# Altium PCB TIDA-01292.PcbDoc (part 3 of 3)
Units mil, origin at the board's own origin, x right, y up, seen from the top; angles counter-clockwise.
Board outline 6102.36 x 3543.31 mil, 2 copper layers (Top Layer, Bottom Layer), stack 64.8 mil thick; 118 components, 43 nets, 376 pads, 3910 vias.
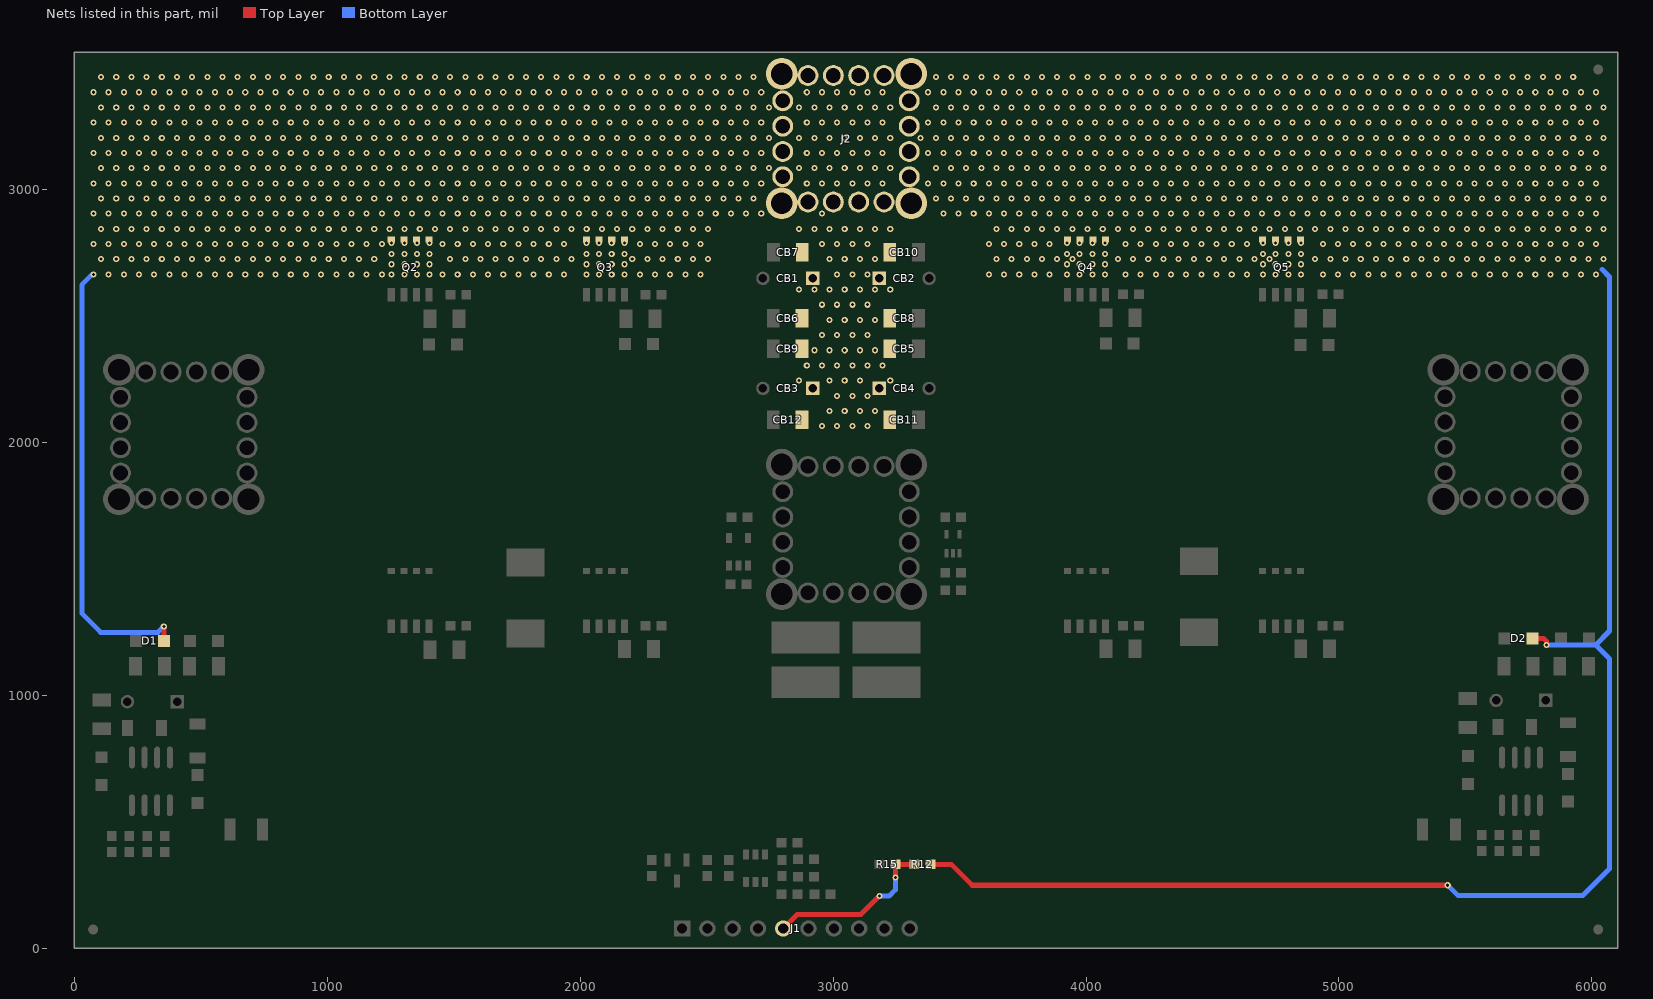
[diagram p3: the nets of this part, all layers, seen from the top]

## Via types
v1: diameter 24, hole 12, Top Layer to Bottom Layer, 3910 vias

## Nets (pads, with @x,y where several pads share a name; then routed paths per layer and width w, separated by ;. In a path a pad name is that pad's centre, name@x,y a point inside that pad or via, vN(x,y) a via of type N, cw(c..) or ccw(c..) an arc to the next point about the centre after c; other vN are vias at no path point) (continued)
VBAT: CB1.1 CB2.1 CB3.1 CB4.1 CB5.1 CB6.1 CB7.1 CB8.1 CB9.1 CB10.1 CB11.1 CB12.1 D1.2 D2.2 J2.1 pad.1@2797.2,2946.03 pad.1@2797.2,3457.84 pad.1@3309.01,2946.03 pad.1@3309.01,3457.84 Q2.5 Q2.6 Q2.7 Q2.8 Q3.5 Q3.6 Q3.7 Q3.8 Q4.5 Q4.6 Q4.7 Q4.8 Q5.5 Q5.6 Q5.7 Q5.8 R12.2 | length 7261.9
  Top Layer w20: D1.2@354.1,1215.6 v1(354.1,1273.6) ; R12.2@3384.65,337.74 R12.2@3384.65,332.74 3467.26,332.74 3550,250 v1(5430,250) ; D2.2@5765.12,1225.51 5809.49,1225.51 5820,1215 v1(5820,1200)
  Bottom Layer w20: v1@71.15,2665 30,2623.85 30,1325 105,1250 330.5,1250 v1(354.1,1273.6) ; v1(5430,250) 5470,210 5965,210 6070,315 6070,1145 6015,1200 ; v1(5820,1200) 6015,1200 ; 6040,2685 6070,2655 6070,1255 6015,1200
  other v1: 2956.15,2065 3016.15,2065 3076.15,2065 3136.15,2065 2986.15,2125 3046.15,2125 3106.15,2125 3166.15,2125 3016.15,2185 3076.15,2185 3136.15,2185 2866.15,2245 2986.15,2245 3046.15,2245 3106.15,2245 3226.15,2245 2896.15,2305 2956.15,2305 3016.15,2305 3076.15,2305 3136.15,2305 3196.15,2305 2926.15,2365 2986.15,2365 3046.15,2365 3106.15,2365 3166.15,2365 2956.15,2425 3016.15,2425 3076.15,2425 3136.15,2425 2986.15,2485 3046.15,2485 3106.15,2485 3166.15,2485 2956.15,2545 3016.15,2545 3076.15,2545 3136.15,2545 2866.15,2605 2926.15,2605 2986.15,2605 3046.15,2605 3106.15,2605 3166.15,2605 3226.15,2605 76.15,2665 136.15,2665 196.15,2665 256.15,2665 316.15,2665 376.15,2665 436.15,2665 496.15,2665 556.15,2665 616.15,2665 676.15,2665 736.15,2665 796.15,2665 856.15,2665 916.15,2665 976.15,2665 1036.15,2665 1096.15,2665 1156.15,2665 1216.15,2665 1255,2665 1305,2665 1355,2665 1405,2665 1456.15,2665 1516.15,2665 1576.15,2665 1636.15,2665 1696.15,2665 1756.15,2665 1816.15,2665 1876.15,2665 1936.15,2665 2025,2665 2075,2665 2125,2665 2175,2665 2236.15,2665 2296.15,2665 2356.15,2665 2416.15,2665 2476.15,2665 3016.15,2665 3076.15,2665 3136.15,2665 3616.15,2665 3676.15,2665 3736.15,2665 3796.15,2665 3856.15,2665 3925,2665 3975,2665 4025,2665 4075,2665 4156.15,2665 4216.15,2665 4276.15,2665 4336.15,2665 4396.15,2665 4456.15,2665 4516.15,2665 4576.15,2665 4636.15,2665 4700,2665 4750,2665 4800,2665 4850,2665 4936.15,2665 4996.15,2665 5056.15,2665 5116.15,2665 5176.15,2665 5236.15,2665 5296.15,2665 5356.15,2665 5416.15,2665 5476.15,2665 5536.15,2665 5596.15,2665 5656.15,2665 5716.15,2665 5776.15,2665 5836.15,2665 5896.15,2665 5956.15,2665 6016.15,2665 1255,2705 1305,2705 1355,2705 1405,2705 2025,2705 2075,2705 2125,2705 2175,2705 3925,2705 3975,2705 4025,2705 4075,2705 4700,2705 4750,2705 4800,2705 4850,2705 106.15,2725 166.15,2725 226.15,2725 286.15,2725 346.15,2725 406.15,2725 466.15,2725 526.15,2725 586.15,2725 646.15,2725 706.15,2725 766.15,2725 826.15,2725 886.15,2725 946.15,2725 1006.15,2725 1066.15,2725 1126.15,2725 1186.15,2725 1486.15,2725 1546.15,2725 1606.15,2725 1666.15,2725 1726.15,2725 1786.15,2725 1846.15,2725 1906.15,2725 1966.15,2725 2206.15,2725 2266.15,2725 2326.15,2725 2386.15,2725 2446.15,2725 2506.15,2725 2986.15,2725 3046.15,2725 3106.15,2725 3166.15,2725 3646.15,2725 3706.15,2725 3766.15,2725 3826.15,2725 3886.15,2725 3946.15,2725 4126.15,2725 4186.15,2725 4246.15,2725 4306.15,2725 4366.15,2725 4426.15,2725 4486.15,2725 4546.15,2725 4606.15,2725 4666.15,2725 4726.15,2725 4906.15,2725 4966.15,2725 5026.15,2725 5086.15,2725 5146.15,2725 5206.15,2725 5266.15,2725 5326.15,2725 5386.15,2725 5446.15,2725 5506.15,2725 5566.15,2725 5626.15,2725 5686.15,2725 5746.15,2725 5806.15,2725 5866.15,2725 5926.15,2725 5986.15,2725 6046.15,2725 1255,2745 1305,2745 1355,2745 1405,2745 2025,2745 2075,2745 2125,2745 2175,2745 3925,2745 3975,2745 4025,2745 4075,2745 4700,2745 4750,2745 4800,2745 4850,2745 76.15,2785 136.15,2785 196.15,2785 256.15,2785 316.15,2785 376.15,2785 436.15,2785 496.15,2785 556.15,2785 616.15,2785 676.15,2785 736.15,2785 796.15,2785 856.15,2785 916.15,2785 976.15,2785 1036.15,2785 1096.15,2785 1156.15,2785 1216.15,2785 1456.15,2785 1516.15,2785 1576.15,2785 1636.15,2785 1696.15,2785 1756.15,2785 1816.15,2785 1876.15,2785 1936.15,2785 2236.15,2785 2296.15,2785 2356.15,2785 2416.15,2785 2476.15,2785 2956.15,2785 3016.15,2785 3076.15,2785 3136.15,2785 3616.15,2785 3676.15,2785 3736.15,2785 3796.15,2785 3856.15,2785 4156.15,2785 4216.15,2785 4276.15,2785 4336.15,2785 4396.15,2785 4456.15,2785 4516.15,2785 4576.15,2785 4636.15,2785 4936.15,2785 4996.15,2785 5056.15,2785 5116.15,2785 5176.15,2785 5236.15,2785 5296.15,2785 5356.15,2785 5416.15,2785 5476.15,2785 5536.15,2785 5596.15,2785 5656.15,2785 5716.15,2785 5776.15,2785 5836.15,2785 5896.15,2785 5956.15,2785 6016.15,2785 1255,2789 1305,2789 1355,2789 1405,2789 2025,2789 2075,2789 2125,2789 2175,2789 3925,2789 3975,2789 4025,2789 4075,2789 4700,2789 4750,2789 4800,2789 4850,2789 106.15,2845 166.15,2845 226.15,2845 286.15,2845 346.15,2845 406.15,2845 466.15,2845 526.15,2845 586.15,2845 646.15,2845 706.15,2845 766.15,2845 826.15,2845 886.15,2845 946.15,2845 1006.15,2845 1066.15,2845 1126.15,2845 1186.15,2845 1246.15,2845 1306.15,2845 1366.15,2845 1426.15,2845 1486.15,2845 1546.15,2845 1606.15,2845 1666.15,2845 1726.15,2845 1786.15,2845 1846.15,2845 1906.15,2845 1966.15,2845 2026.15,2845 2086.15,2845 2146.15,2845 2206.15,2845 2266.15,2845 2326.15,2845 2386.15,2845 2446.15,2845 2506.15,2845 2866.15,2845 2926.15,2845 2986.15,2845 3046.15,2845 3106.15,2845 3166.15,2845 3226.15,2845 3646.15,2845 3706.15,2845 3766.15,2845 3826.15,2845 3886.15,2845 3946.15,2845 4006.15,2845 4066.15,2845 4126.15,2845 4186.15,2845 4246.15,2845 4306.15,2845 4366.15,2845 4426.15,2845 4486.15,2845 4546.15,2845 4606.15,2845 4666.15,2845 4726.15,2845 4786.15,2845 4846.15,2845 4906.15,2845 4966.15,2845 5026.15,2845 5086.15,2845 5146.15,2845 5206.15,2845 5266.15,2845 5326.15,2845 5386.15,2845 5446.15,2845 5506.15,2845 5566.15,2845 5626.15,2845 5686.15,2845 5746.15,2845 5806.15,2845 5866.15,2845 5926.15,2845 5986.15,2845 6046.15,2845 76.15,2905 136.15,2905 196.15,2905 256.15,2905 316.15,2905 376.15,2905 436.15,2905 496.15,2905 556.15,2905 616.15,2905 676.15,2905 736.15,2905 796.15,2905 856.15,2905 916.15,2905 976.15,2905 1036.15,2905 1096.15,2905 1156.15,2905 1216.15,2905 1276.15,2905 1336.15,2905 1396.15,2905 1456.15,2905 1516.15,2905 1576.15,2905 1636.15,2905 1696.15,2905 1756.15,2905 1816.15,2905 1876.15,2905 1936.15,2905 1996.15,2905 2056.15,2905 2116.15,2905 2176.15,2905 2236.15,2905 2296.15,2905 2356.15,2905 2416.15,2905 2476.15,2905 2536.15,2905 2596.15,2905 2656.15,2905 2716.15,2905 2956.15,2905 3436.15,2905 3496.15,2905 3556.15,2905 3616.15,2905 3676.15,2905 3736.15,2905 3796.15,2905 3856.15,2905 3916.15,2905 3976.15,2905 4036.15,2905 4096.15,2905 4156.15,2905 4216.15,2905 4276.15,2905 4336.15,2905 4396.15,2905 4456.15,2905 4516.15,2905 4576.15,2905 4636.15,2905 4696.15,2905 4756.15,2905 4816.15,2905 4876.15,2905 4936.15,2905 4996.15,2905 5056.15,2905 5116.15,2905 5176.15,2905 5236.15,2905 5296.15,2905 5356.15,2905 5416.15,2905 5476.15,2905 5536.15,2905 5596.15,2905 5656.15,2905 5716.15,2905 5776.15,2905 5836.15,2905 5896.15,2905 5956.15,2905 6016.15,2905 106.15,2965 166.15,2965 226.15,2965 286.15,2965 346.15,2965 406.15,2965 466.15,2965 526.15,2965 586.15,2965 646.15,2965 706.15,2965 766.15,2965 826.15,2965 886.15,2965 946.15,2965 1006.15,2965 1066.15,2965 1126.15,2965 1186.15,2965 1246.15,2965 1306.15,2965 1366.15,2965 1426.15,2965 1486.15,2965 1546.15,2965 1606.15,2965 1666.15,2965 1726.15,2965 1786.15,2965 1846.15,2965 1906.15,2965 1966.15,2965 2026.15,2965 2086.15,2965 2146.15,2965 2206.15,2965 2266.15,2965 2326.15,2965 2386.15,2965 2446.15,2965 2506.15,2965 2566.15,2965 2626.15,2965 2686.15,2965 3406.15,2965 3466.15,2965 3526.15,2965 3586.15,2965 3646.15,2965 3706.15,2965 3766.15,2965 3826.15,2965 3886.15,2965 3946.15,2965 4006.15,2965 4066.15,2965 4126.15,2965 4186.15,2965 4246.15,2965 4306.15,2965 4366.15,2965 4426.15,2965 4486.15,2965 4546.15,2965 4606.15,2965 4666.15,2965 4726.15,2965 4786.15,2965 4846.15,2965 4906.15,2965 4966.15,2965 5026.15,2965 5086.15,2965 5146.15,2965 5206.15,2965 5266.15,2965 5326.15,2965 5386.15,2965 5446.15,2965 5506.15,2965 5566.15,2965 5626.15,2965 5686.15,2965 5746.15,2965 5806.15,2965 5866.15,2965 5926.15,2965 5986.15,2965 6046.15,2965 76.15,3025 136.15,3025 196.15,3025 256.15,3025 316.15,3025 376.15,3025 436.15,3025 496.15,3025 556.15,3025 616.15,3025 676.15,3025 736.15,3025 796.15,3025 856.15,3025 916.15,3025 976.15,3025 1036.15,3025 1096.15,3025 1156.15,3025 1216.15,3025 1276.15,3025 1336.15,3025 1396.15,3025 1456.15,3025 1516.15,3025 1576.15,3025 1636.15,3025 1696.15,3025 1756.15,3025 1816.15,3025 1876.15,3025 1936.15,3025 1996.15,3025 2056.15,3025 2116.15,3025 2176.15,3025 2236.15,3025 2296.15,3025 2356.15,3025 2416.15,3025 2476.15,3025 2536.15,3025 2596.15,3025 2656.15,3025 2716.15,3025 2896.15,3025 2956.15,3025 3016.15,3025 3076.15,3025 3136.15,3025 3196.15,3025 3376.15,3025 3436.15,3025 3496.15,3025 3556.15,3025 3616.15,3025 3676.15,3025 3736.15,3025 3796.15,3025 3856.15,3025 3916.15,3025 3976.15,3025 4036.15,3025 4096.15,3025 4156.15,3025 4216.15,3025 4276.15,3025 4336.15,3025 4396.15,3025 4456.15,3025 4516.15,3025 4576.15,3025 4636.15,3025 4696.15,3025 4756.15,3025 4816.15,3025 4876.15,3025 4936.15,3025 4996.15,3025 5056.15,3025 5116.15,3025 5176.15,3025 5236.15,3025 5296.15,3025 5356.15,3025 5416.15,3025 5476.15,3025 5536.15,3025 5596.15,3025 5656.15,3025 5716.15,3025 5776.15,3025 5836.15,3025 5896.15,3025 5956.15,3025 6016.15,3025 106.15,3085 166.15,3085 226.15,3085 286.15,3085 346.15,3085 406.15,3085 466.15,3085 526.15,3085 586.15,3085 646.15,3085 706.15,3085 766.15,3085 826.15,3085 886.15,3085 946.15,3085 1006.15,3085 1066.15,3085 1126.15,3085 1186.15,3085 1246.15,3085 1306.15,3085 1366.15,3085 1426.15,3085 1486.15,3085 1546.15,3085 1606.15,3085 1666.15,3085 1726.15,3085 1786.15,3085 1846.15,3085 1906.15,3085 1966.15,3085 2026.15,3085 2086.15,3085 2146.15,3085 2206.15,3085 2266.15,3085 2326.15,3085 2386.15,3085 2446.15,3085 2506.15,3085 2566.15,3085 2626.15,3085 2686.15,3085 2746.15,3085 2866.15,3085 2926.15,3085 2986.15,3085 3046.15,3085 3106.15,3085 3166.15,3085 3226.15,3085 3406.15,3085 3466.15,3085 3526.15,3085 3586.15,3085 3646.15,3085 3706.15,3085 3766.15,3085 3826.15,3085 3886.15,3085 3946.15,3085 4006.15,3085 4066.15,3085 4126.15,3085 4186.15,3085 4246.15,3085 4306.15,3085 4366.15,3085 4426.15,3085 4486.15,3085 4546.15,3085 4606.15,3085 4666.15,3085 4726.15,3085 4786.15,3085 4846.15,3085 4906.15,3085 4966.15,3085 5026.15,3085 5086.15,3085 5146.15,3085 5206.15,3085 5266.15,3085 5326.15,3085 5386.15,3085 5446.15,3085 5506.15,3085 5566.15,3085 5626.15,3085 5686.15,3085 5746.15,3085 5806.15,3085 5866.15,3085 5926.15,3085 5986.15,3085 6046.15,3085 76.15,3145 136.15,3145 196.15,3145 256.15,3145 316.15,3145 376.15,3145 436.15,3145 496.15,3145 556.15,3145 616.15,3145 676.15,3145 736.15,3145 796.15,3145 856.15,3145 916.15,3145 976.15,3145 1036.15,3145 1096.15,3145 1156.15,3145 1216.15,3145 1276.15,3145 1336.15,3145 1396.15,3145 1456.15,3145 1516.15,3145 1576.15,3145 1636.15,3145 1696.15,3145 1756.15,3145 1816.15,3145 1876.15,3145 1936.15,3145 1996.15,3145 2056.15,3145 2116.15,3145 2176.15,3145 2236.15,3145 2296.15,3145 2356.15,3145 2416.15,3145 2476.15,3145 2536.15,3145 2596.15,3145 2656.15,3145 2716.15,3145 2896.15,3145 2956.15,3145 3016.15,3145 3076.15,3145 3136.15,3145 3196.15,3145 3376.15,3145 3436.15,3145 3496.15,3145 3556.15,3145 3616.15,3145 3676.15,3145 3736.15,3145 3796.15,3145 3856.15,3145 3916.15,3145 3976.15,3145 4036.15,3145 4096.15,3145 4156.15,3145 4216.15,3145 4276.15,3145 4336.15,3145 4396.15,3145 4456.15,3145 4516.15,3145 4576.15,3145 4636.15,3145 4696.15,3145 4756.15,3145 4816.15,3145 4876.15,3145 4936.15,3145 4996.15,3145 5056.15,3145 5116.15,3145 5176.15,3145 5236.15,3145 5296.15,3145 5356.15,3145 5416.15,3145 5476.15,3145 5536.15,3145 5596.15,3145 5656.15,3145 5716.15,3145 5776.15,3145 5836.15,3145 5896.15,3145 5956.15,3145 6016.15,3145 106.15,3205 166.15,3205 226.15,3205 286.15,3205 346.15,3205 406.15,3205 466.15,3205 526.15,3205 586.15,3205 646.15,3205 706.15,3205 766.15,3205 826.15,3205 886.15,3205 946.15,3205 1006.15,3205 1066.15,3205 1126.15,3205 1186.15,3205 1246.15,3205 1306.15,3205 1366.15,3205 1426.15,3205 1486.15,3205 1546.15,3205 1606.15,3205 1666.15,3205 1726.15,3205 1786.15,3205 1846.15,3205 1906.15,3205 1966.15,3205 2026.15,3205 2086.15,3205 2146.15,3205 2206.15,3205 2266.15,3205 2326.15,3205 2386.15,3205 2446.15,3205 2506.15,3205 2566.15,3205 2626.15,3205 2686.15,3205 2746.15,3205 2866.15,3205 2926.15,3205 2986.15,3205 3046.15,3205 3106.15,3205 3166.15,3205 3226.15,3205 3346.15,3205 3406.15,3205 3466.15,3205 3526.15,3205 3586.15,3205 3646.15,3205 3706.15,3205 3766.15,3205 3826.15,3205 3886.15,3205 3946.15,3205 4006.15,3205 4066.15,3205 4126.15,3205 4186.15,3205 4246.15,3205 4306.15,3205 4366.15,3205 4426.15,3205 4486.15,3205 4546.15,3205 4606.15,3205 4666.15,3205 4726.15,3205 4786.15,3205 4846.15,3205 4906.15,3205 4966.15,3205 5026.15,3205 5086.15,3205 5146.15,3205 5206.15,3205 5266.15,3205 5326.15,3205 5386.15,3205 5446.15,3205 5506.15,3205 5566.15,3205 5626.15,3205 5686.15,3205 5746.15,3205 5806.15,3205 5866.15,3205 5926.15,3205 5986.15,3205 6046.15,3205 76.15,3265 136.15,3265 196.15,3265 256.15,3265 316.15,3265 376.15,3265 436.15,3265 496.15,3265 556.15,3265 616.15,3265 676.15,3265 736.15,3265 796.15,3265 856.15,3265 916.15,3265 976.15,3265 1036.15,3265 1096.15,3265 1156.15,3265 1216.15,3265 1276.15,3265 1336.15,3265 1396.15,3265 1456.15,3265 1516.15,3265 1576.15,3265 1636.15,3265 1696.15,3265 1756.15,3265 1816.15,3265 1876.15,3265 1936.15,3265 1996.15,3265 2056.15,3265 2116.15,3265 2176.15,3265 2236.15,3265 2296.15,3265 2356.15,3265 2416.15,3265 2476.15,3265 2536.15,3265 2596.15,3265 2656.15,3265 2716.15,3265 2896.15,3265 2956.15,3265 3016.15,3265 3076.15,3265 3136.15,3265 3196.15,3265 3376.15,3265 3436.15,3265 3496.15,3265 3556.15,3265 3616.15,3265 3676.15,3265 3736.15,3265 3796.15,3265 3856.15,3265 3916.15,3265 3976.15,3265 4036.15,3265 4096.15,3265 4156.15,3265 4216.15,3265 4276.15,3265 4336.15,3265 4396.15,3265 4456.15,3265 4516.15,3265 4576.15,3265 4636.15,3265 4696.15,3265 4756.15,3265 4816.15,3265 4876.15,3265 4936.15,3265 4996.15,3265 5056.15,3265 5116.15,3265 5176.15,3265 5236.15,3265 5296.15,3265 5356.15,3265 5416.15,3265 5476.15,3265 5536.15,3265 5596.15,3265 5656.15,3265 5716.15,3265 5776.15,3265 5836.15,3265 5896.15,3265 5956.15,3265 6016.15,3265 106.15,3325 166.15,3325 226.15,3325 286.15,3325 346.15,3325 406.15,3325 466.15,3325 526.15,3325 586.15,3325 646.15,3325 706.15,3325 766.15,3325 826.15,3325 886.15,3325 946.15,3325 1006.15,3325 1066.15,3325 1126.15,3325 1186.15,3325 1246.15,3325 1306.15,3325 1366.15,3325 1426.15,3325 1486.15,3325 1546.15,3325 1606.15,3325 1666.15,3325 1726.15,3325 1786.15,3325 1846.15,3325 1906.15,3325 1966.15,3325 2026.15,3325 2086.15,3325 2146.15,3325 2206.15,3325 2266.15,3325 2326.15,3325 2386.15,3325 2446.15,3325 2506.15,3325 2566.15,3325 2626.15,3325 2686.15,3325 2746.15,3325 2866.15,3325 2926.15,3325 2986.15,3325 3046.15,3325 3106.15,3325 3166.15,3325 3226.15,3325 3406.15,3325 3466.15,3325 3526.15,3325 3586.15,3325 3646.15,3325 3706.15,3325 3766.15,3325 3826.15,3325 3886.15,3325 3946.15,3325 4006.15,3325 4066.15,3325 4126.15,3325 4186.15,3325 4246.15,3325 4306.15,3325 4366.15,3325 4426.15,3325 4486.15,3325 4546.15,3325 4606.15,3325 4666.15,3325 4726.15,3325 4786.15,3325 4846.15,3325 4906.15,3325 4966.15,3325 5026.15,3325 5086.15,3325 5146.15,3325 5206.15,3325 5266.15,3325 5326.15,3325 5386.15,3325 5446.15,3325 5506.15,3325 5566.15,3325 5626.15,3325 5686.15,3325 5746.15,3325 5806.15,3325 5866.15,3325 5926.15,3325 5986.15,3325 6046.15,3325 76.15,3385 136.15,3385 196.15,3385 256.15,3385 316.15,3385 376.15,3385 436.15,3385 496.15,3385 556.15,3385 616.15,3385 676.15,3385 736.15,3385 796.15,3385 856.15,3385 916.15,3385 976.15,3385 1036.15,3385 1096.15,3385 1156.15,3385 1216.15,3385 1276.15,3385 1336.15,3385 1396.15,3385 1456.15,3385 1516.15,3385 1576.15,3385 1636.15,3385 1696.15,3385 1756.15,3385 1816.15,3385 1876.15,3385 1936.15,3385 1996.15,3385 2056.15,3385 2116.15,3385 2176.15,3385 2236.15,3385 2296.15,3385 2356.15,3385 2416.15,3385 2476.15,3385 2536.15,3385 2596.15,3385 2656.15,3385 2716.15,3385 2896.15,3385 2956.15,3385 3016.15,3385 3076.15,3385 3136.15,3385 3196.15,3385 3376.15,3385 3436.15,3385 3496.15,3385 3556.15,3385 3616.15,3385 3676.15,3385 3736.15,3385 3796.15,3385 3856.15,3385 3916.15,3385 3976.15,3385 4036.15,3385 4096.15,3385 4156.15,3385 4216.15,3385 4276.15,3385 4336.15,3385 4396.15,3385 4456.15,3385 4516.15,3385 4576.15,3385 4636.15,3385 4696.15,3385 4756.15,3385 4816.15,3385 4876.15,3385 4936.15,3385 4996.15,3385 5056.15,3385 5116.15,3385 5176.15,3385 5236.15,3385 5296.15,3385 5356.15,3385 5416.15,3385 5476.15,3385 5536.15,3385 5596.15,3385 5656.15,3385 5716.15,3385 5776.15,3385 5836.15,3385 5896.15,3385 5956.15,3385 6016.15,3385 106.15,3445 166.15,3445 226.15,3445 286.15,3445 346.15,3445 406.15,3445 466.15,3445 526.15,3445 586.15,3445 646.15,3445 706.15,3445 766.15,3445 826.15,3445 886.15,3445 946.15,3445 1006.15,3445 1066.15,3445 1126.15,3445 1186.15,3445 1246.15,3445 1306.15,3445 1366.15,3445 1426.15,3445 1486.15,3445 1546.15,3445 1606.15,3445 1666.15,3445 1726.15,3445 1786.15,3445 1846.15,3445 1906.15,3445 1966.15,3445 2026.15,3445 2086.15,3445 2146.15,3445 2206.15,3445 2266.15,3445 2326.15,3445 2386.15,3445 2446.15,3445 2506.15,3445 2566.15,3445 2626.15,3445 2686.15,3445 3406.15,3445 3466.15,3445 3526.15,3445 3586.15,3445 3646.15,3445 3706.15,3445 3766.15,3445 3826.15,3445 3886.15,3445 3946.15,3445 4006.15,3445 4066.15,3445 4126.15,3445 4186.15,3445 4246.15,3445 4306.15,3445 4366.15,3445 4426.15,3445 4486.15,3445 4546.15,3445 4606.15,3445 4666.15,3445 4726.15,3445 4786.15,3445 4846.15,3445 4906.15,3445 4966.15,3445 5026.15,3445 5086.15,3445 5146.15,3445 5206.15,3445 5266.15,3445 5326.15,3445 5386.15,3445 5446.15,3445 5506.15,3445 5566.15,3445 5626.15,3445 5686.15,3445 5746.15,3445 5806.15,3445 5866.15,3445 5926.15,3445
VOUT: J1.5 R12.1 R15.2 | length 682.6
  Top Layer w20: J1.5@2803.15,79 2858.15,134 3109.41,134 v1(3183.15,207.74) ; v1(3246.14,280.73) R15.2@3246.14,332.74 R12.1@3321.65,332.74
  Bottom Layer w20: v1(3183.15,207.74) 3221.89,207.74 3246.14,231.99 v1(3246.14,280.73)
pads on no net: FID1.1 FID2.1 FID3.1 H1.0 H2.0 H3.0 H4.0 U2.4 U2.5

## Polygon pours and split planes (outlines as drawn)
VBAT on Top Layer "VBAT_L01_P060" (solid, remove dead copper, pour order 60): 35,3525 6065,3525 6075,3515 6075,2665 6060,2650 3642.43,2650 3590,2650 3575,2665 3575,2860 3560,2875 3417.43,2875 3275,2875 3250,2850 3250,2050 3225,2025 2874.01,2025 2850,2049.01 2850,2850 2825,2875 2755,2875 2545,2875 2525,2855 2525,2660 2510,2645 40,2645 25,2660 25,3515
GND on Top Layer "GND_L01_P056" (solid, remove dead copper, pour order 56): 25,1285 25,195 25,45 45,25 650,25 670,45 670,1285 655,1300 40,1300
GND on Top Layer "GND_L01_P054" (solid, remove dead copper, pour order 54): 5410,1270 5410,180 5410,45 5430,25 5620,25 6050,25 6075,50 6075,225 6075,1270 6060,1285 5425,1285
GND on Top Layer "GND_L01_P050" (solid, remove dead copper, pour order 50): 2795,2825 2775,2845 2565,2845 2550,2830 2550,1795 2560,1785 2705,1785 2720,1770 2720,1300 2730,1290 2730,1175 2740,1165 3365,1165 3375,1175 3375,1295 3380,1300 3380,1525 3390,1535 3469,1535 3483,1549 3483,1644 3472,1655 3390,1655 3380,1665 3380,1770 3395,1785 3540,1785 3550,1795 3550,2835 3540,2845 3320,2845 3310,2835 3310,2010 3295,1995 2810,1995 2795,2010
"COMMON A" on Top Layer "COMMON_A_L01_P006" (solid, remove dead copper, pour order 6): 110,2615 1350,2615 1365,2600 1365,2345 1385,2325 1600,2325 1620,2345 1620,2530 1604.15,2545.85 1544.15,2545.85 1530,2560 1530,2611.89 2123.11,2611.89 2135,2600 2135,2345 2155,2325 2375,2325 2395,2345 2395,2535 2380,2550 2310,2550 2303.15,2556.85 2303.15,2603.15 2310,2610 2515,2610 2525,2600 2525,1375 2490,1340 115,1340 100,1355 100,2605
"COMMON B" on Top Layer "COMMON_B_L01_P008" (solid, remove dead copper, pour order 8): 3590,2615 4035,2615 4035,2350 4060,2325 4260,2325 4285,2350 4285,2530 4265,2550 4200,2550 4190,2560 4190,2615 4800,2615 4810,2605 4810,2340 4825,2325 5040,2325 5055,2340 5055,2540 5045,2550 4985,2550 4975,2560 4975,2615 5990,2615 6000,2605 6000,1365 5980,1345 3590,1345 3575,1360 3575,2600
NetC20_1 on Top Layer "NETC20_1_L01_P010" (solid, remove dead copper, pour order 10): 1368.9,1300 1368.9,1121.1 1380,1110 1550,1110 1560,1120 1560,1245.86 1525,1245.86 1525,1300 2140,1300 2140,1125 2160,1105 2315,1105 2335,1125 2335,1230 2325,1240 2295,1240 2295,1300 2685,1300 2700,1285 2700,1145 2724.15,1120.85 3378.15,1120.85 3400,1142.7 3400,1280 3420,1300 4040,1300 4040,1130 4060,1110 4215,1110 4235,1130 4235,1245 4185,1245 4185,1300 4810,1300 4810,1125 4830,1105 4990,1105 5005,1120 5005,1240 5000,1245 4980,1245 4975,1250 4975,1295 4980,1300 5365,1300 5380,1285 5380,430 5370,420 710,420 700,430 700,1285 715,1300
GND on Bottom Layer "GND_L02_P042" (solid, remove dead copper, pour order 42): 45,25 6075,25 6075,1285 6060,1300 5440,1300 5410,1270 5410,420 5385,395 699.98,395.02 670,425 670,1285 655,1300 40,1300 25,1285 25,45
GND on Bottom Layer "GND_L02_P052" (solid, remove dead copper, pour order 52): 2795,2825 2775,2845 2565,2845 2550,2830 2550,1795 2560,1785 2705,1785 2720,1770 2720,1300 2730,1290 2730,1175 2740,1165 3365,1165 3375,1175 3375,1295 3380,1300 3380,1525 3390,1535 3470,1535 3478,1543 3478,1642 3465,1655 3390,1655 3380,1665 3380,1770 3395,1785 3540,1785 3550,1795 3550,2835 3540,2845 3320,2845 3310,2835 3310,2010 3295,1995 2810,1995 2795,2010
NetC20_1 on Bottom Layer "NETC20_1_L02_P048" (solid, remove dead copper, pour order 48): 715,1300 700,1285 700,430 710,420 5370,420 5380,430 5380,1270 5350,1300
"COMMON B" on Bottom Layer "COMMON_B_L02_P046" (solid, remove dead copper, pour order 46): 3590,2615 3575,2600 3575,1360 3590,1345 5980,1345 6000,1365 6000,2605 5990,2615 3600,2615
"COMMON A" on Bottom Layer "COMMON_A_L02_P044" (solid, remove dead copper, pour order 44): 110,2615 100,2605 100,1355 115,1340 2490,1340 2525,1375 2525,2600 2515,2610 2510,2615 110,2615
VBAT on Bottom Layer "VBAT_L02_P018" (solid, remove dead copper, pour order 18): 35,3525 6065,3525 6075,3515 6075,2665 6060,2650 3642.43,2650 3590,2650 3575,2665 3575,2860 3560,2875 3417.43,2875 3275,2875 3250,2850 3250,2050 3225,2025 2874.01,2025 2850,2049.01 2850,2850 2825,2875 2755,2875 2545,2875 2525,2855 2525,2660 2510,2645 40,2645 25,2660 25,3515

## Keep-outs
Keep-Out Layer:
  the board outline again, w10

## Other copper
Top Layer:
  rectangle net GND: 3467,1546 3483,1580
  pour cut-out: 2358.65,451.82 3756.15,451.82 3756.15,368.18 2359.2,368.18
  text ".Layer_Name" at 380.15,-859.49 h60
Bottom Layer:
  pour cut-out: 3028.15,1125.85 3028.15,495.85 2963.15,430.85 2963.15,395.85 2968.15,390.85 3033.15,390.85 3058.15,415.85 3058.15,1125.85
  text ".Layer_Name" at 380.15,-859.49 h60

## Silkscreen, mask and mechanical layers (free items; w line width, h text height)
Top Overlay:
  circle w10: c3863.61,1276.26 r8.54
  circle w10: c4638.61,1276.26 r8.54
  circle w10: c4638.61,2586.26 r8.54
  circle w10: c1963.39,1275.85 r8.54
  circle w10: c1193.39,1275.85 r8.54
  circle w10: c1963.39,2585.85 r8.54
  circle w10: c1193.39,2580.85 r8.54
  circle w10: c3868.61,2586.26 r8.54
  lines w2: 132.96,2030.97 133.04,2030.89 ; 432.46,1731.97 432.96,1732.47 ; 2753.11,1655.93 2753.19,1655.85 ; 2753.11,3200.93 2753.19,3200.85 ; 3035.61,2901.93 3036.11,2902.43 ; 3052.61,1356.93 3053.11,1357.43 ; 5368.87,2031.27 5368.96,2031.19 ; 5668.37,1732.27 5668.87,1732.77
  lines w6: 132.96,1831.97 132.96,2229.97 ; 247.96,1731.97 616.96,1731.97 ; 247.96,2331.97 617.96,2331.97 ; 732.96,1831.97 732.96,2229.81 ; 2753.11,1456.93 2753.11,1854.93 ; 2753.11,3001.93 2753.11,3399.93 ; 2851.11,1956.93 3221.11,1956.93 ; 2851.11,2901.93 3220.11,2901.93 ; 2868.11,1356.93 3237.11,1356.93 ; 2868.11,3501.93 3238.11,3501.93 ; 3353.11,1456.93 3353.11,1854.77 ; 3353.11,3001.93 3353.11,3399.77 ; 5368.87,1832.27 5368.87,2230.27 ; 5483.87,1732.27 5852.87,1732.27 ; 5483.87,2332.27 5853.87,2332.27 ; 5968.87,1832.27 5968.87,2230.11
  text "TIDA-01292-E1" at 3578.15,270.85 h60
  text ".Layer_Name" at 380.15,-859.49 h60
Bottom Overlay:
  text ".Layer_Name" at 380.15,-859.49 h60
Top Paste:
  text ".Layer_Name" at 380.15,-859.49 h60
Bottom Paste:
  text ".Layer_Name" at 380.15,-859.49 h60
Top Solder:
  text ".Layer_Name" at 380.15,-859.49 h60
  text ".Layer_Name" at 380.15,-859.49 h60
Bottom Solder:
  region: 1165,2990 1165,2645 1495,2645 1495,2990
  region: 1940,2990 1940,2645 2270,2645 2270,2990
  region: 1940,1690 1940,1345 2270,1345 2270,1690
  region: 1165,1690 1165,1345 1495,1345 1495,1690
  region: 4610,2995 4610,2650 4940,2650 4940,2995
  region: 3840,2995 3840,2650 4170,2650 4170,2995
  region: 4610,1690 4610,1345 4940,1345 4940,1690
  region: 3840,1690 3840,1345 4170,1345 4170,1690
  text ".Layer_Name" at 380.15,-859.49 h60
M1 Board Outline:
  the board outline again, w10
M2 Board Dimensions:
  rectangle: -71.85,-401 303.15,-276
  rectangle: -196.85,-276 -71.85,-151
  lines w7: -196.85,-276 803.15,-276 ; -71.85,-401 -71.85,-151 ; 53.15,-401 53.15,-151 ; 303.15,-401 303.15,-151 ; 553.15,-401 553.15,-151 ; -196.85,-401 -196.85,-151 803.15,-151 803.15,-401 -196.85,-401
M3 3D STEP Top:
  text ".Layer_Name" at 380.15,-859.49 h60
M4 3D STEP Bottom:
  text ".Layer_Name" at 380.15,-859.49 h60
M5 Assembly Top:
  circle w10: c2589,1490 r10
  circle w10: c2423.15,352.74 r7.07
  lines w10: -488.85,-931.17 6111.15,-931.17 ; -488.85,-727.83 6113.15,-727.83 ; -488.85,-524.5 -488.85,-1134.5 3516.15,-1134.5 6113.15,-1134.5 6113.15,-524.5 -488.35,-524.5 -488.35,-1134.5 1087.15,-1134.5 ; 1976.15,-1134.5 1976.15,-524.5 ; 3243.15,-727.83 3243.15,-524.5 ; 4083.15,-727.83 4083.15,-524.5 ; 4705.15,-1141 4705.15,-938.17
  text "COMPONENTS MARKED 'DNP' SHOULD NOT BE POPULATED." at 956.65,-319.5 h30
  text "ASSEMBLY VARIANT:" at 956.15,-435 h30
  text ".VariantName" at 1992.15,-435 h30
  text "PCB VIEWED FROM TOP SIDE" at -425.35,-656.67 h30
  text "BOARD #:" at 2051.15,-656.67 h30
  text ".PRJ_Number" at 2596.65,-656.67 h30
  text "REV:" at 3441.15,-656.67 h30
  text ".PCB_Rev" at 3732.65,-656.67 h30
  text "SVN REV:" at 4279.15,-656.67 h30
  text ".VersionControl_RevNumber" at 4785.15,-656.67 h30
  text "TID #:" at 2051.15,-860 h30
  text ".TID" at 2596.65,-860 h30
  text ".layer_Name" at 383.15,-861 h30
  text "PLOT NAME =" at -425.35,-1065.34 h30
  text ".plot_File_Name" at 380.15,-1065.34 h30
  text "GENERATED    :" at 2053.15,-1065.34 h30
  text ".Print_Date" at 2922.65,-1065.34 h30
  text ".Print_Time" at 3651.65,-1065.34 h30
  text "TEXAS INSTRUMENTS" at 4916.15,-1065.34 h30
M6 Assembly Bottom:
  lines w10: -489.35,-728.33 6112.65,-728.33 ; -487.35,-931.67 6112.65,-931.67 ; 918.65,-1141.5 918.65,-938.67 ; 1540.65,-728.33 1540.65,-525 ; 2380.65,-728.33 2380.65,-525 ; 3647.65,-1135 3647.65,-525 ; 4536.65,-1135 6112.15,-1135 6112.15,-525 -489.35,-525 -489.35,-1135 2107.65,-1135 6112.65,-1135 6112.65,-525
  text "COMPONENTS MARKED 'DNP' SHOULD NOT BE POPULATED." at 5905.15,-319 h30
  text ".VariantName" at 4861.15,-435 h30
  text "ASSEMBLY VARIANT:" at 5900.15,-435 h30
  text ".VersionControl_RevNumber" at 838.65,-657.17 h30
  text "SVN REV:" at 1344.65,-657.17 h30
  text ".PCB_Rev" at 1891.15,-657.17 h30
  text "REV:" at 2182.65,-657.17 h30
  text ".PRJ_Number" at 3027.15,-657.17 h30
  text "BOARD #:" at 3572.65,-657.17 h30
  text "PCB VIEWED FROM BOTTOM SIDE" at 6049.15,-657.17 h30
  text ".TID" at 3027.15,-860.5 h30
  text "TID #:" at 3572.65,-860.5 h30
  text ".layer_Name" at 5163.15,-861 h30
  text "TEXAS INSTRUMENTS" at 707.65,-1065.84 h30
  text ".Print_Time" at 1972.15,-1065.84 h30
  text ".Print_Date" at 2701.15,-1065.84 h30
  text "GENERATED    :" at 3570.65,-1065.84 h30
  text ".plot_File_Name" at 5243.65,-1065.84 h30
  text "PLOT NAME =" at 6049.15,-1065.84 h30
M9 Title Sheet:
  drawing of 57 lines, arcs and shapes, not listed
  text "1" at 542.99,8035.5 h70
  text "2" at 3038.65,8035.5 h70
  text "3" at 5527.99,8035.5 h70
  text "4" at 8034.66,8035.5 h70
  text "5" at 10533.65,8035.5 h70
  text "6" at 13038.65,8035.5 h70
  text "A" at -613.35,6892.5 h70
  text "A" at 14186.65,6892.5 h70
  text "B" at -613.35,4512.5 h70
  text "B" at 14186.65,4512.5 h70
  text "C" at -613.35,2137.5 h70
  text "C" at 14186.65,2137.5 h70
  text "PROJECT TITLE:" at 11146.65,276.5 h45
  text ".PRJ_Title" at 11196.65,143.17 h70
  text "DESIGNED FOR:" at 11146.65,-24.5 h45
  text ".PRJ_Customer" at 11196.65,-164.5 h70
  text "D" at -613.35,-232.5 h70
  text "D" at 14186.65,-232.5 h70
  text "FILE NAME:" at 11146.65,-324.5 h45
  text ".PCB_File_Name_No_Path" at 11196.65,-444.5 h70
  text "Texas Instruments (TI) and/or its licensors do not warrant the accuracy or completeness of this specification" at 6177.15,-606.34 h45
  text "ENGINEER:" at 11146.65,-614.5 h45
  text "LAYOUT BY:" at 12651.65,-614.5 h45
  text "or any information contained therein. TI and/or its licensors do not warrant that this design will meet" at 6132.16,-719 h45
  text ".PRJ_Engineer" at 11196.65,-769.49 h70
  text ".PCB_Layout" at 12702.15,-769.49 h70
  text "the specifications, will be suitable for your application or fit for any particular purpose, or will operate in" at 6132.16,-831.67 h45
  text "ALTIUM DESIGNER VERSION:" at 12651.65,-924.5 h45
  text "an implementation. TI and/or its licensors do not warrant that the design is production worthy. You should" at 6132.16,-944.33 h45
  text "completely validate and test your design implementation to confirm the system functionality for your application." at 6177.15,-1057 h45
  text ".print_Scale" at 11196.65,-1057.83 h70
  text ".Application_BuildNumber" at 12702.15,-1057.83 h70
  text "1" at 542.99,-1264.5 h70
  text "2" at 3038.65,-1264.5 h70
  text "3" at 5527.99,-1264.5 h70
  text "4" at 8034.66,-1264.5 h70
  text "5" at 10533.65,-1264.5 h70
  text "6" at 13038.65,-1264.5 h70
M10 Fab Notes:
  drawing of 191 lines, arcs and shapes, not listed
  text "DESIGN INFORMATION" at 12189.17,6689 h60
  text "(REFER ALSO ARRAY/PANEL PROFILING INFORMATION)" at 11827.61,6527.29 h60
  text "BOARD SIZE" at 11141.61,6523 h60
  text "X" at 12109.61,6395.18 h60
  text "90MM" at 12345.15,6388 h60
  text "155MM" at 11620.15,6386.7 h60
  text "Number of Layers :" at 11559.61,6288 h60
  text "2" at 12654.42,6278 h60
  text "MIN. TRACK WIDTH:" at 11559.61,6149 h60
  text "15" at 12629.15,6149.4 h60
  text "MIL" at 12810.61,6149 h60
  text "6" at 12673,6026 h60
  text "MIN. CLEARANCE:" at 11559.61,6017 h60
  text "MIL" at 12828.15,5990.4 h60
  text "MIN. VIA PAD SIZE:" at 11559.61,5885 h60
  text "24" at 12640.15,5885.4 h60
  text "MIL" at 12828.15,5862.4 h60
  text "0.152mm (6MIL)" at 12254.61,5743.29 h60
  text "EXTERNAL" at 12991.15,5743.4 h60
  text "MINIMUM ANNULAR RING" at 11230.38,5739.01 h60
  text "PER" at 11430.38,5621 h60
  text "IPC-D-275 CLASS 2 LEVEL C" at 11650.38,5621 h60
  text "MIL, HOLES" at 13138.61,5508.71 h60
  text "+/-" at 12746.15,5508 h60
  text "+/-" at 13600.15,5508 h60
  text "REGISTRATION TOLERANCES:" at 11230.38,5503 h60
  text "METAL" at 12430.15,5503 h60
  text "5" at 13006.35,5503 h60
  text "3" at 13839.35,5503 h60
  text "MIL" at 13955.61,5503 h60
  text "IMPEDENCE CONTROLLED BOARD:NO" at 11263.15,5354 h60
  text "MATERIAL:" at 11139.61,5130.54 h60
  text "FR-4 High Tg" at 12126.05,4990.21 h60
  text "FR-408" at 11560.61,4981.64 h60
  text "OTHER" at 13048.61,4981.64 h60
  text "X" at 11964.15,4980 h60
  text "THICKNESS:" at 11141.15,4825 h60
  text "63 MIL (1.6mm) +/-10%" at 11800.15,4820 h60
  text "OTHER" at 13165.61,4814.64 h60
  text "X" at 11665.15,4812 h60
  text "TOLERANCE:" at 11214.38,4656.64 h60
  text "X" at 12053.68,4656.64 h60
  text "ANSI IPC-6012 TYPE 3 CLASS 2" at 12240.63,4656.64 h60
  text "OTHER +/-" at 12240.61,4500.64 h60
  text "BOW & TWIST:" at 11214.38,4343.64 h60
  text "X" at 12053.68,4343.64 h60
  text "ANSI IPC-6012 TYPE 3 CLASS 2" at 12240.63,4343.64 h60
  text "OTHER +/-" at 12240.61,4185.13 h60
  text "DRILLING:" at 11139.61,4046.64 h60
  text "REFERENCE:" at 11214.38,3929.64 h60
  text "X" at 11862.61,3929.64 h60
  text "AS SHOWN" at 12049.61,3929.64 h60
  text "X" at 12763.61,3929.64 h60
  text "NC_DRILL FILES" at 12900.61,3929.64 h60
  text "PTH MIN COPPER THICKNESS:" at 11214.38,3771.64 h60
  text "X" at 12564.61,3771.64 h60
  text "1MIL" at 12701.61,3771.64 h60
  text "OTHER" at 13198.61,3771.64 h60
  text "BOARD FINISH:" at 11139.61,3612.64 h60
  text "SILKSCREEN:" at 11294.83,3494.64 h60
  text "X" at 12243.61,3494.64 h60
  text "TOP" at 12369.61,3494.64 h60
  text "X" at 12753.61,3494.64 h60
  text "BOTTOM" at 12880.61,3494.64 h60
  text "SILKSCREEN COLOR:" at 11294.83,3327.64 h60
  text "X" at 12242.57,3327.64 h60
  text "WHITE" at 12369.61,3327.64 h60
  text "OTHER" at 12880.61,3327.64 h60
  text "SOLDER RESIST COLOR:" at 11294.83,3157.64 h60
  text "X" at 11862.57,2998.44 h60
  text "GREEN" at 11989.61,2998.44 h60
  text "BLUE" at 12580.61,2998.44 h60
  text "OTHER" at 13118.61,2998.44 h60
  text "IMMERSION GOLD (ENIG)" at 12200.61,2809.92 h60
  text "ENEPIG" at 13538.15,2806.64 h60
  text "SURFACE FINISH:" at 11139.61,2805.64 h60
  text "X" at 12013.66,2805.64 h60
  text "IMM. TIN/SILVER OR EQUIV" at 11469.15,2648.64 h60
  text "OTHER" at 12900.61,2648.64 h60
  text "ARRAY/PANEL:" at 11139.61,2469.64 h60
  text "CUT AND TRIM PER MECH LAYER 1" at 12200.61,2465.35 h60
  text "N.C. ROUTE" at 12200.61,2313.64 h60
  text "X" at 12879.61,2313.64 h60
  text "V. SCORE" at 13066.61,2313.64 h60
  text "CERTIFICATION:" at 11139.61,2176.64 h60
  text "MATERIALS AND WORKMANSHIP FOR ALL PCBS" at 11864.61,2176.64 h60
  text "TO MEET OR EXCEED THE REQUIREMENTS OF:" at 11864.61,2078.64 h60
  text "X" at 11491.11,1942.14 h60
  text "ANSI IPC-A-600F CLASS ->" at 11630.11,1942.14 h60
  text "X" at 13269.17,1942.14 h60
  text "2" at 13388.11,1942.14 h60
  text "1" at 13073.11,1940.64 h60
  text "3" at 13742.11,1940.64 h60
  text "X" at 11493.17,1782.64 h60
  text "UL 94V-0" at 11630.11,1782.64 h60
  text "X" at 12305.17,1782.64 h60
  text "RoHS" at 12442.11,1782.64 h60
  text "OTHER" at 13086.51,1782.64 h60
  text "PER ORDER" at 13483.57,1782.64 h60
  text "ADDITIONAL REQUIREMENTS:" at 11139.61,1641.64 h60
  text "MICROSECTION:" at 11214.38,1526.64 h60
  text "YES" at 12120.11,1526.64 h60
  text "REQUIRED" at 12981.61,1370.5 h60
  text "BARE BOARD ELEC. TEST:" at 11214.38,1367.64 h60
  text "NONE" at 12520.11,1367.64 h60
  text "X" at 12854.61,1367.64 h60
  text "PER ORDER" at 13573.61,1367.64 h60
  text "MANUFACTURER'S UL:" at 11214.38,1210.64 h60
  text "RAIL" at 12380.11,1206.35 h60
  text "METAL" at 12871.92,1206.35 h60
  text "X" at 13247.15,1206 h60
  text "SILK" at 13383.61,1206.35 h60
  text "VIA`S TO BE TENTED:" at 11194.15,1019 h60
  text "NO" at 12099.15,1019 h60
M11 Gerber Information:
  lines w10: -488.85,-931.17 6111.15,-931.17 ; -488.85,-727.83 6113.15,-727.83 ; -488.85,-524.5 -488.85,-1134.5 3516.15,-1134.5 6113.15,-1134.5 6113.15,-524.5 -488.35,-524.5 -488.35,-1134.5 1087.15,-1134.5 ; 1976.15,-1134.5 1976.15,-524.5 ; 3243.15,-727.83 3243.15,-524.5 ; 4083.15,-727.83 4083.15,-524.5 ; 4705.15,-1141 4705.15,-938.17
  text "ALL ARTWORK VIEWED FROM TOP SIDE" at -425.35,-656.67 h60
  text "BOARD #:" at 2051.15,-656.67 h60
  text ".PRJ_Number" at 2596.65,-656.67 h60
  text "REV:" at 3441.15,-656.67 h60
  text ".PCB_Rev" at 3732.65,-656.67 h60
  text "SVN REV:" at 4279.15,-656.67 h60
  text ".VersionControl_RevNumber" at 4785.15,-656.67 h60
  text "LAYER NAME =" at -425.35,-859.49 h60
  text "TID #:" at 2051.15,-860 h60
  text ".TID" at 2596.65,-860 h60
  text "PLOT NAME =" at -425.35,-1065.34 h60
  text ".plot_File_Name" at 380.15,-1065.34 h60
  text "GENERATED    :" at 2053.15,-1065.34 h60
  text ".Print_Date" at 2922.65,-1065.34 h60
  text ".Print_Time" at 3651.65,-1065.34 h60
  text "TEXAS INSTRUMENTS" at 4916.15,-1065.34 h60
M12 Stackup:
  drawing of 191 lines, arcs and shapes, not listed
  text "Layer" at 9518.15,7755.7 h60
  text "Name" at 9928.06,7755.7 h60
  text "Material" at 10857.81,7755.7 h60
  text "Thickness" at 11717.57,7755.7 h60
  text "Constant" at 12367.41,7755.7 h60
  text "Board Layer Stack" at 12937.27,7755.7 h60
  text "1" at 9518.15,7635.7 h60
  text "Top Overlay" at 9928.06,7635.7 h60
  text "2" at 9518.15,7515.7 h60
  text "Top Solder" at 9928.06,7515.7 h60
  text "Solder Resist" at 10857.81,7515.7 h60
  text "0.40mil" at 11717.57,7515.7 h60
  text "3.5" at 12367.41,7515.7 h60
  text "3" at 9518.15,7395.7 h60
  text "Top Layer" at 9928.06,7395.7 h60
  text "Copper" at 10857.81,7395.7 h60
  text "2.80mil" at 11717.57,7395.7 h60
  text "4" at 9518.15,7275.7 h60
  text "Dielectric1" at 9928.06,7275.7 h60
  text "FR-4 High Tg" at 10857.81,7275.7 h60
  text "59.20mil" at 11717.57,7275.7 h60
  text "4.8" at 12367.41,7275.7 h60
  text "5" at 9518.15,7155.7 h60
  text "Bottom Layer" at 9928.06,7155.7 h60
  text "Copper" at 10857.81,7155.7 h60
  text "2.80mil" at 11717.57,7155.7 h60
  text "6" at 9518.15,7035.7 h60
  text "Bottom Solder" at 9928.06,7035.7 h60
  text "Solder Resist" at 10857.81,7035.7 h60
  text "0.40mil" at 11717.57,7035.7 h60
  text "3.5" at 12367.41,7035.7 h60
  text "7" at 9518.15,6915.7 h60
  text "Bottom Overlay" at 9928.06,6915.7 h60
M13 Component Bodies Top:
  text ".Layer_Name" at 380.15,-859.49 h60
M14 Component Bodies Bottom:
  text ".Layer_Name" at 380.15,-859.49 h60
M15 Courtyards Top:
  text ".Layer_Name" at 380.15,-859.49 h60
M16 Courtyards Bottom:
  text ".Layer_Name" at 380.15,-859.49 h60
Drill Drawing:
  lines w10: 6540.44,1062.25 6573.77,1078.92 6607.11,1062.25 6590.44,1095.59 6607.11,1128.92 6573.77,1112.25 6540.44,1128.92 6557.11,1095.59 6540.44,1062.25 ; 6540.44,1212.25 6540.44,1228.92 6557.11,1245.59 6540.44,1262.25 6540.44,1278.92 6557.11,1278.92 6573.77,1262.25 6590.44,1278.92 6607.11,1278.92 6607.11,1262.25 6590.44,1245.59 6607.11,1228.92 6607.11,1212.25 6590.44,1212.25 6573.77,1228.92 6557.11,1212.25 6540.44,1212.25 ; 6540.44,1362.25 6607.11,1362.25 6607.11,1428.92 6540.44,1428.92 6540.44,1362.25 ; 6540.44,1578.92 6607.11,1578.92 6573.77,1512.25 6540.44,1578.92 ; 6540.44,1662.25 6607.11,1662.25 6607.11,1728.92 6540.44,1728.92 6540.44,1662.25 ; 6553.77,1675.59 6593.77,1675.59 6593.77,1715.59 6553.77,1715.59 6553.77,1675.59
  lines w15: 6480.65,1017.25 10359.62,1017.25 ; 6480.65,1767.25 10359.62,1767.25 ; 7031.53,867.25 7031.53,1917.25 ; 7729.34,867.25 7729.34,1917.25 ; 9074.94,867.25 9074.94,1917.25 ; 9580.82,867.25 9580.82,1917.25 ; 6480.65,867.25 10359.62,867.25 10359.62,1917.25 6480.65,1917.25 6480.65,867.25
  text "DRILL TABLE" at 6485,1975 h60
  text "Symbol" at 6570.65,1812.25 h72
  text "Hit Count" at 7076.53,1812.25 h72
  text "Finished Hole Size" at 7774.34,1812.25 h72
  text "Plated" at 9119.94,1812.25 h72
  text "Hole Type" at 9625.82,1812.25 h72
  text "3910" at 7076.53,1662.25 h60
  text "12.00mil (0.30500mm)" at 7774.34,1662.25 h60
  text "PTH" at 9119.94,1662.25 h60
  text "Round" at 9625.82,1662.25 h60
  text "80" at 7076.53,1512.25 h60
  text "58.07mil (1.47500mm)" at 7774.34,1512.25 h60
  text "PTH" at 9119.94,1512.25 h60
  text "Round" at 9625.82,1512.25 h60
  text "16" at 7076.53,1362.25 h60
  text "86.61mil (2.20000mm)" at 7774.34,1362.25 h60
  text "PTH" at 9119.94,1362.25 h60
  text "Round" at 9625.82,1362.25 h60
  text "12" at 7076.53,1212.25 h60
  text "33.46mil (0.85000mm)" at 7774.34,1212.25 h60
  text "PTH" at 9119.94,1212.25 h60
  text "Round" at 9625.82,1212.25 h60
  text "10" at 7076.53,1062.25 h60
  text "40.00mil (1.01600mm)" at 7774.34,1062.25 h60
  text "PTH" at 9119.94,1062.25 h60
  text "Round" at 9625.82,1062.25 h60
  text "4028 Total" at 7076.53,912.25 h60
  text "FOR PTH +3/-3MIL" at 6478.15,745.85 h60
  text "FOR 12MIL DRILL +0/-12MIL" at 6477,624 h60
  text "Copper thickness is 2oz." at 6475,505 h60
  text "This is not an Impedence control board." at 6467,376 h60
  text ".Layer_Name" at 380.15,-859.49 h60
M17 Embedded Cavity:
  text ".Layer_Name" at 380.15,-859.49 h60
M18 Embedded Assembly:
  text ".Layer_Name" at 380.15,-859.49 h60
M19 Embedded Keepout:
  text ".Layer_Name" at 380.15,-859.49 h60

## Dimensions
0,3543.31 to 0,0 on M2 Board Dimensions
-196.85,-401 to 803.15,-401 on M2 Board Dimensions
0,0 to 6102.36,0 on M2 Board Dimensions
